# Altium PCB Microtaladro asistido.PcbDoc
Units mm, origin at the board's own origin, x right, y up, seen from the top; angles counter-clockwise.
Board outline 86.69 x 80.16 mm, 2 copper layers (Top Layer, Bottom Layer); 41 components, 54 nets, 188 pads, 36 vias.
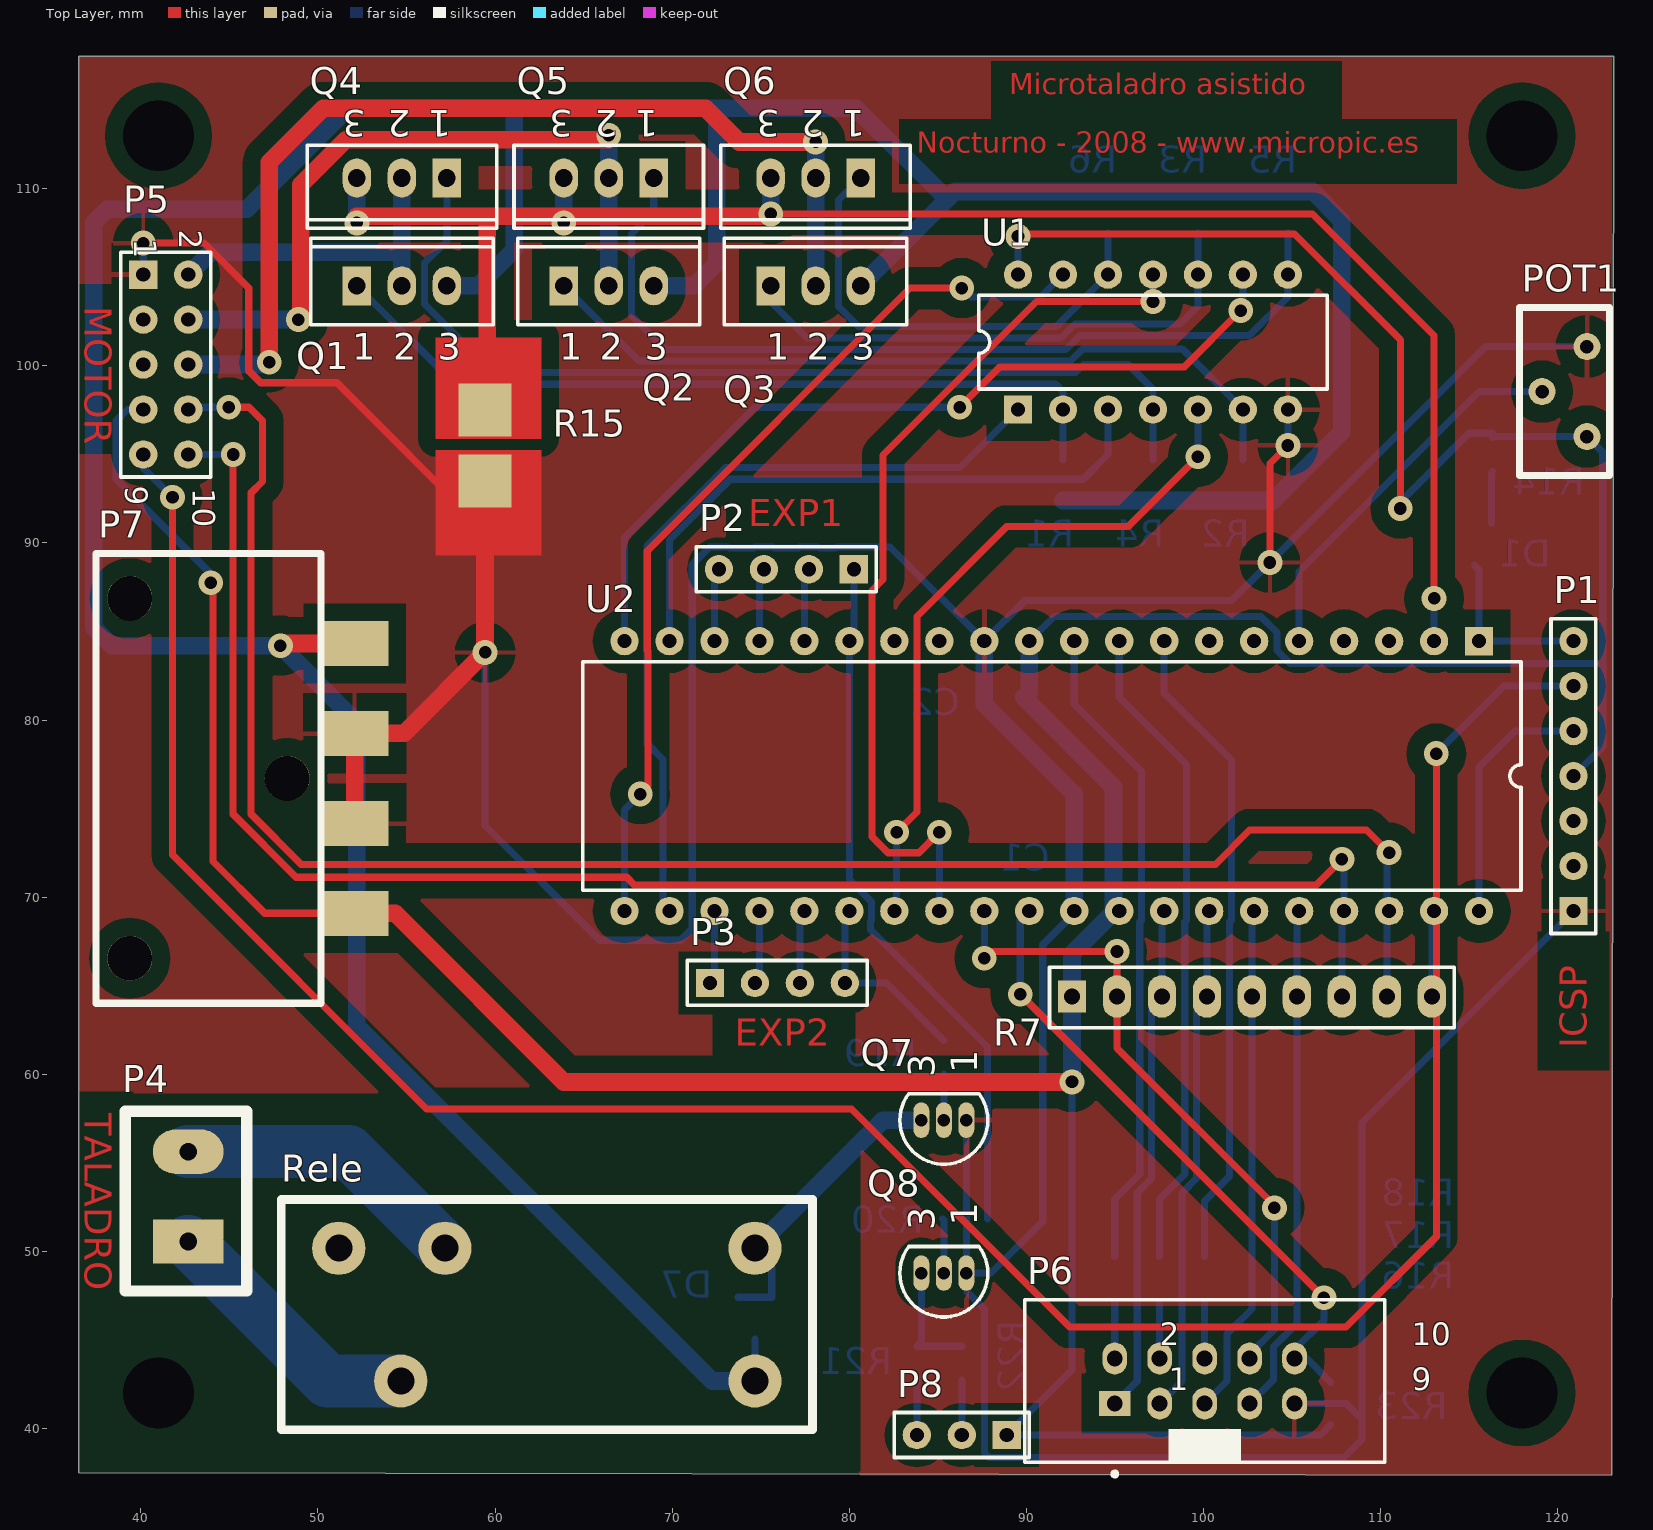
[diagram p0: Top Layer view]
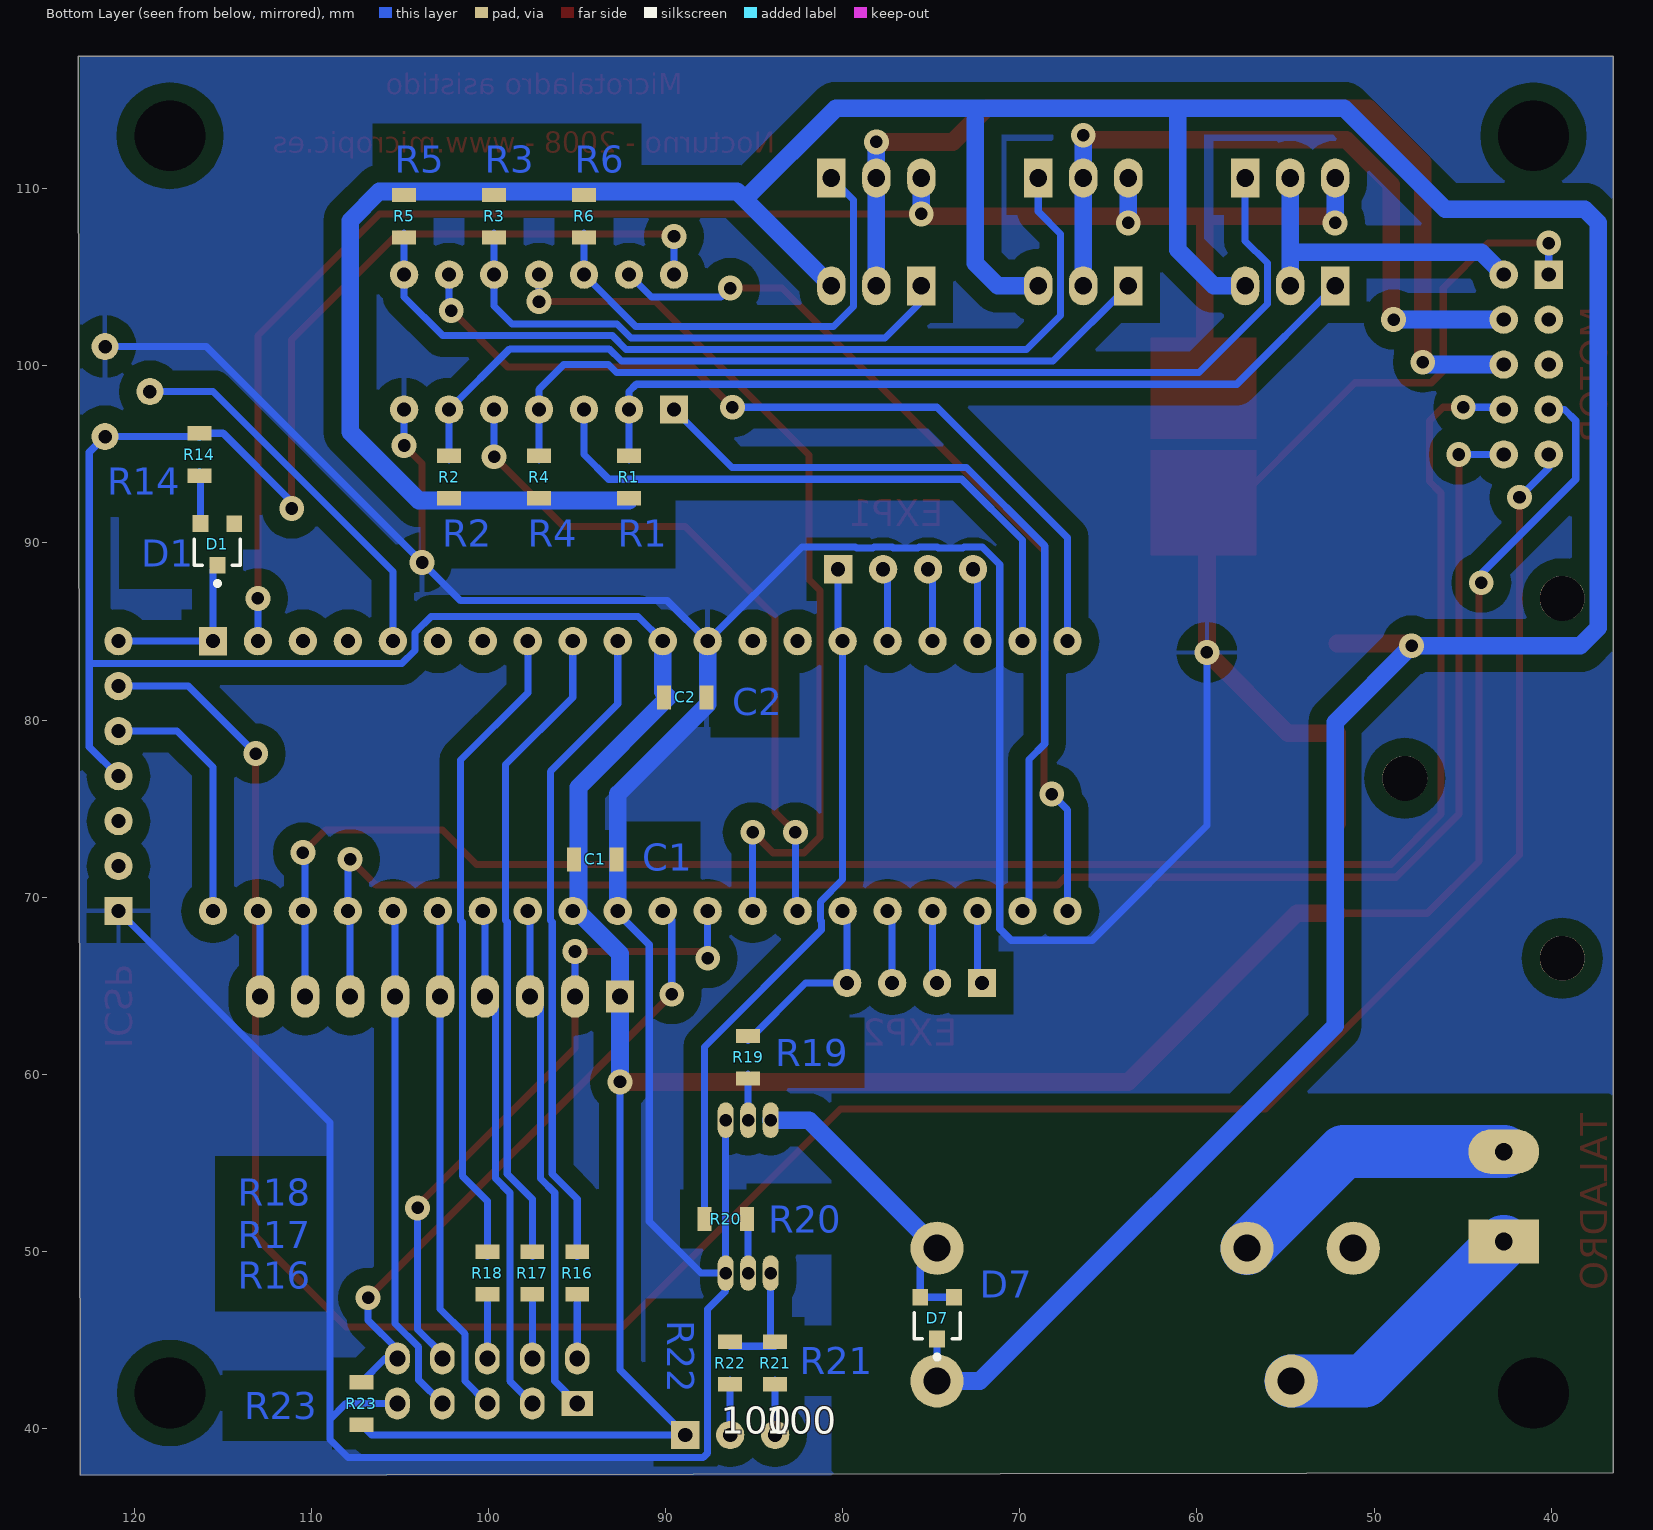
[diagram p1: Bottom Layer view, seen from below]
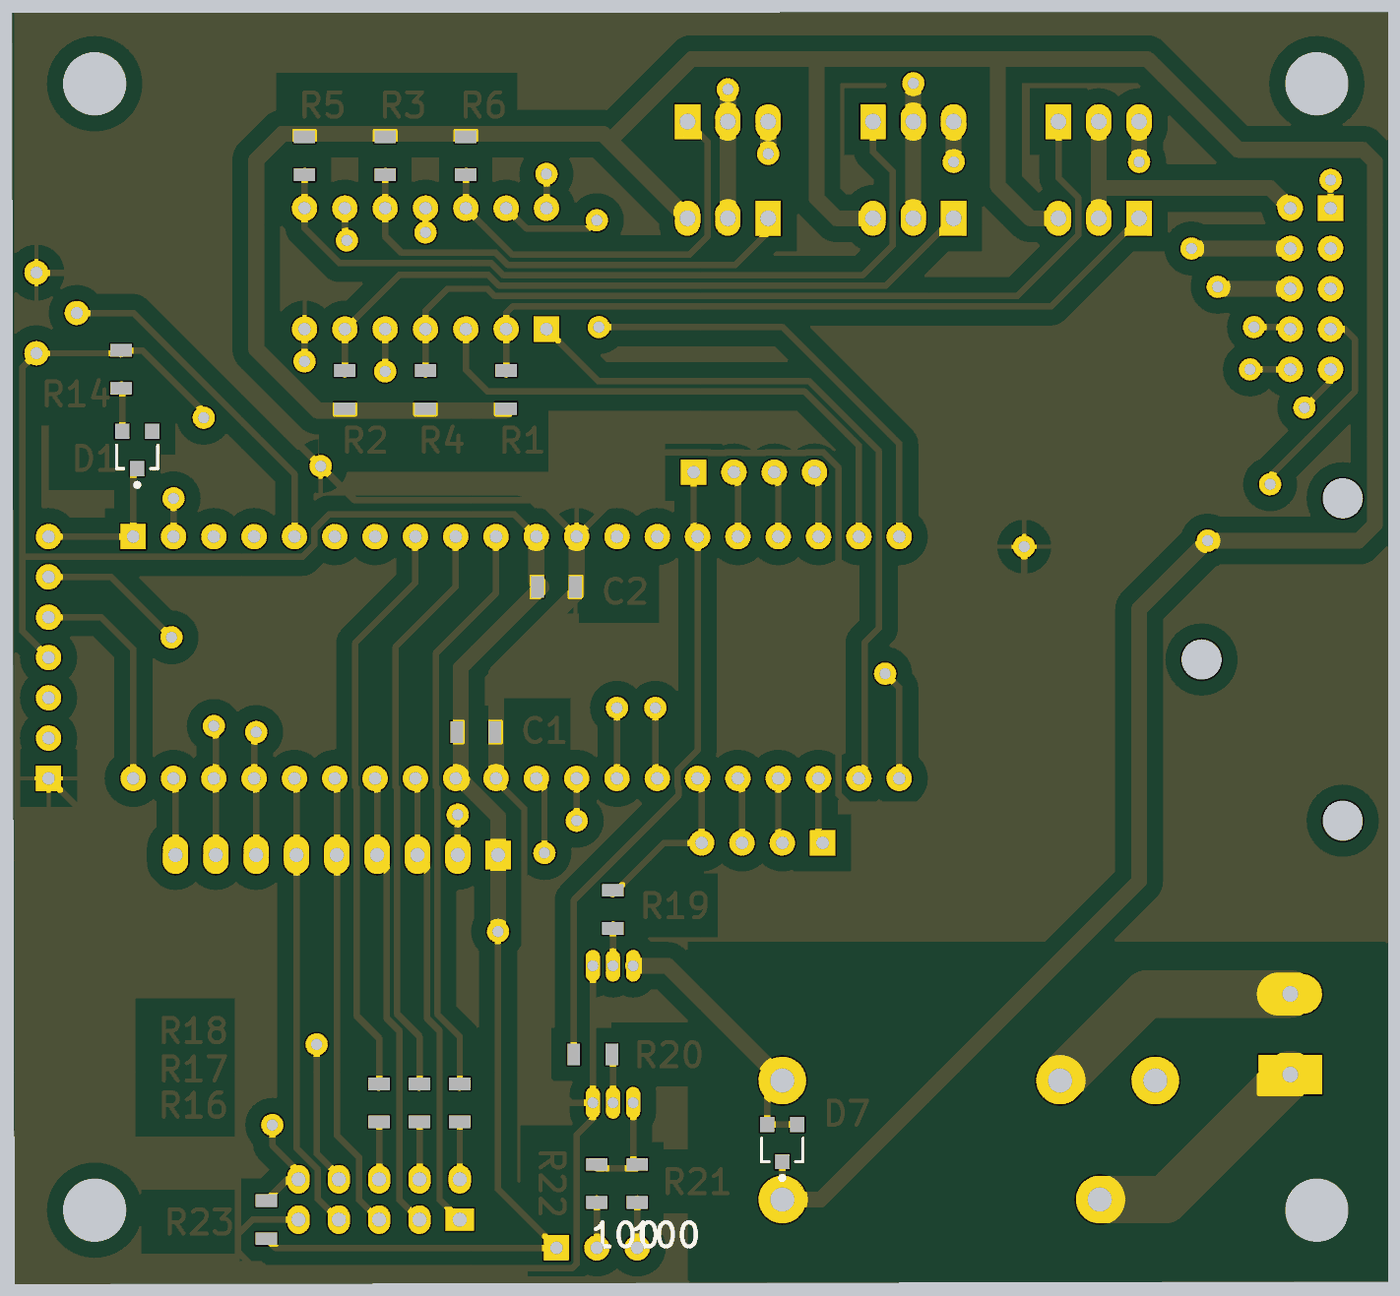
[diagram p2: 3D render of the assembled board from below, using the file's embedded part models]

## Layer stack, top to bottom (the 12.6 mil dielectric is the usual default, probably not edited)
Top Layer: signal copper 0.0356
Dielectric: dielectric 0.32, FR-4, Dk 4.8
Bottom Layer: signal copper 0.0356

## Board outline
36.5,37.5 123.063,37.338 123.19,117.475 36.5,117.5

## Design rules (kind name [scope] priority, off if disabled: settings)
Clearance [All] p1: gap=0.254
HoleSize [All] p1: absolutevalues=TRUE maxlimit=4 minlimit=0.025 maxpercent=80.000 minpercent=20.000
PolygonConnect [All] p1: connectstyle=Relief reliefconductorwidth=0.254 reliefentries=4 polygonreliefangle="90 Angle"
RoutingVias [All] p1: holewidth=0.6 width=1.4 viastyle="Through Hole" minholewidth=0.6 minwidth=1.4 maxholewidth=4 maxwidth=1.6
SilkscreenOverComponentPads [All] p1: minsilkscreentomaskgap=0.254
SolderMaskExpansion [All] p1: expansion=0.102
TestPointUsage [All] p1: valid=0 allowmultiple=FALSE
Testpoint [All] p1: side=15 testpointundercomponent=TRUE minsize=1.016 maxsize=2.54 preferedsize=1.524 minholesize=0 maxholesize=1.016 preferedholesize=0.813 testpointgrid=0.025 style=1023 order=0123456789
Width [All] p1: maxlimit=3 minlimit=0.254 preferedwidth=0.254 toplayer_prefwidth=0.4 bottomlayer_prefwidth=0.4 minimp=50.000000 maximp=50.000000 favimp=50.000000
22 further rules are at their usual default settings.

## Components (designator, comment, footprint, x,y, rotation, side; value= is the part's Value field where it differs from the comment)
C1 "100nF" 2012[0805] 93.98,72.136 r0 bottom
C2 "100nF" 2012[0805] 88.9,81.28 r0 bottom
D1 "BAV74" SOT23 115.316,89.916 r0 bottom
D7 "BAV74" SOT23 74.676,46.228 r0 bottom
P1 "ICSP" HDR1X7 120.904,69.215 r90 top
P2 "EXP1" HDR1X4 80.264,88.519 r180 top
P3 "EXP2" HDR1X4 72.136,65.151 r0 top
P4 "Taladro" Clema-2 42.672,46.736 r90 top
P5 "Motor" HDR2X5 40.132,105.156 r270 top
P6 "Pulsadores y leds" 918510X324 100.076,42.672 r0 top
P7 "Alimentación" "CONECTOR ALIMENTACIóN" 48.26,76.708 r90 top
P8 "Iluminación" HDR1X3 88.9,39.624 r180 top
POT1 "RPot SM" PCBComponent_1 120.396,98.552 r90 top
Q1 "TIP125" 221A-02 54.737,104.521 r0 top
Q2 "TIP125" 221A-02 66.421,104.521 r0 top
Q3 "TIP125" 221A-02 78.105,104.521 r0 top
Q4 "IRF531" TO-220AB 54.737,110.617 r180 top
Q5 "IRF531" TO-220AB 66.421,110.617 r180 top
Q6 "IRF531" TO-220AB 78.105,110.617 r180 top
Q7 "2N3904" TO-92A 85.344,57.404 r90 top
Q8 "2N3904" TO-92A 85.344,48.768 r90 top
R1 "4K7" 2012[0805] 92.075,93.726 r270 bottom
R2 "4K7" 2012[0805] 102.235,93.726 r270 bottom
R3 "4K7" 2012[0805] 99.695,108.458 r90 bottom
R4 "47K" 2012[0805] 97.155,93.726 r270 bottom
R5 "47K" 2012[0805] 104.775,108.458 r90 bottom
R6 "47K" 2012[0805] 94.615,108.458 r90 bottom
R7 "8 x 4K7" "ARRAY RESISTENCIAS SIP9" 103.124,64.516 r0 top
R14 "4K7" 2012[0805] 116.332,94.996 r90 bottom
R15 "0,1" "0603 Shunt" 59.436,95.504 r90 top
R16 "470" 2012[0805] 94.996,48.768 r90 bottom
R17 "470" 2012[0805] 97.536,48.768 r90 bottom
R18 "470" 2012[0805] 100.076,48.768 r90 bottom
R19 "10K" 2012[0805] 85.344,60.96 r90 bottom
R20 "10K" 2012[0805] 86.614,51.816 r0 bottom
R21 "100" 2012[0805] 83.82,43.688 r90 bottom
R22 "100" 2012[0805] 86.36,43.688 r90 bottom
R23 "4K7" 2012[0805] 107.188,41.402 r270 bottom
Rele "Zócalo Finder 95.13" "Zocalo rele" 74.676,42.672 r90 top
U1 "SN7404N" N014 97.155,101.346 r0 top
U2 "PIC18F4539-I/P" PDIP600-40 91.44,76.835 r180 top

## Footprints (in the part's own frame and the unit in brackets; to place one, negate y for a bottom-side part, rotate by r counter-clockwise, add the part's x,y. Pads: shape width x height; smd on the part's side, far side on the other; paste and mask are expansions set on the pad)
221A-02 [mm] "TO, Thru-Hole, Vertical, Heatsink Mounted; 3 In-Line Leads; Pitch 2.54 mm"
  rect 1.6x2.2 hole 1: 1(-2.54,0)
  oval 1.6x2.2 hole 1: 2(0,0) 3(2.54,0)
  silkscreen extent -5.15,-2.2 5.15,2.7
"0603 Shunt" [mm] "Resistencia Shunt 06 x 03 mm"
  rect 3x3 smd: 1(2,0) 2(-2,0)
2012[0805] [mm] "Chip Resistor; Body 2.0 x 1.3 mm (LxW typ)"
  rect 0.8x1.35 smd: 1(-1.2,0) 2(1.2,0)
  body extent -1,-0.62 1,0.64, height 0.43
918510X324 [mm] "Connector; IDC, Low Profile Male Header, Thru-Hole; 10 Position; Vertical; Pitch 2.54 mm; Body 20.32 x 9.2 x 9.45 mm (LxWxH)"
  rect 1.8x1.4 hole 0.9: 1(-5.08,-1.27)
  oval 1.4x1.8 hole 0.9: 2(-5.08,1.27) 3(-2.54,-1.27) 4(-2.54,1.27) 5(0,-1.27) 6(0,1.27) 7(2.54,-1.27) 8(2.54,1.27) 9(5.08,-1.27) 10(5.08,1.27)
  silkscreen extent -10.16,-5.37 10.16,4.6
"ARRAY RESISTENCIAS SIP9" [mm] "Array resistencias SIP9"
  rect 1.6x1.8 hole 0.9: 1(-10.541,-0.127)
  oval 1.6x2.4 hole 0.9: 2(-8.001,-0.127) 3(-5.461,-0.127) 4(-2.921,-0.127) 5(-0.381,-0.127) 6(2.159,-0.127) 7(4.699,-0.127) 8(7.239,-0.127) 9(9.779,-0.127)
  silkscreen extent -11.81,-1.91 11.05,1.52
Clema-2 [mm]
  rect 2.5x4 hole 1: 1(3.81,0)
  oval 2.5x4 hole 1: 2(8.89,0)
  silkscreen extent 1.02,-3.3 11.18,3.56, body extent 0.8,-3.72 11.3,3.98, height 10
"CONECTOR ALIMENTACIóN" [mm] "Conector alimentación"
  round 2.54 hole 2.54 unplated: 0(-10.16,8.89) 0(10.16,8.89)
  round 2.54 hole 2.54 unplated paste+0: 0(0,0)
  rect 2.54x3.81 smd: 1(7.62,-3.81) 2(2.54,-3.81) 3(-2.54,-3.81) 4(-7.62,-3.81)
  silkscreen extent -12.7,-1.91 12.7,10.8
HDR1X3 [mm] "Connector; Header; 3 Position"
  rect 1.6x1.6 hole 0.8: 1(0,0)
  round 1.6 hole 0.8: 2(2.54,0) 3(5.08,0)
  silkscreen extent -1.27,-1.27 6.35,1.27
HDR1X4 [mm] "Connector; Header; 4 Position"
  rect 1.6x1.6 hole 0.8: 1(0,0)
  round 1.6 hole 0.8: 2(2.54,0) 3(5.08,0) 4(7.62,0)
  silkscreen extent -1.27,-1.27 8.89,1.27
HDR1X7 [mm] "Connector; Header; 7 Position"
  rect 1.6x1.6 hole 0.8: 1(0,0)
  round 1.6 hole 0.8: 2(2.54,0) 3(5.08,0) 4(7.62,0) 5(10.16,0) 6(12.7,0) 7(15.24,0)
  silkscreen extent -1.27,-1.27 16.51,1.27
HDR2X5 [mm] "Connector; Header; 5x2 Position"
  rect 1.6x1.6 hole 0.8: 1(0,0)
  round 1.6 hole 0.8: 2(0,2.54) 3(2.54,0) 4(2.54,2.54) 5(5.08,0) 6(5.08,2.54) 7(7.62,0) 8(7.62,2.54) 9(10.16,0) 10(10.16,2.54)
  silkscreen extent -1.27,-1.27 11.43,3.81
N014 [mm] "DIP; 14 Leads; Row Spacing 7.62 mm; Pitch 2.54 mm"
  rect 1.6x1.6 hole 0.8: 1(-7.62,-3.81)
  round 1.6 hole 0.8: 2(-5.08,-3.81) 3(-2.54,-3.81) 4(0,-3.81) 5(2.54,-3.81) 6(5.08,-3.81) 7(7.62,-3.81) 8(7.62,3.81) 9(5.08,3.81) 10(2.54,3.81) 11(0,3.81) 12(-2.54,3.81) 13(-5.08,3.81) 14(-7.62,3.81)
  silkscreen extent -9.85,-2.65 9.85,2.65
PCBComponent_1 [mil]
  round 60 hole 30: CCW(100,-50) CW(-100,-50) W(0,50)
  silkscreen extent -187,-100 187,100
PDIP600-40 [mm] "DIP, Plastic; 40 Leads; Row Spacing 15.24 mm; Pitch 2.54 mm"
  rect 1.6x1.6 hole 0.8: 1(-24.13,-7.62)
  round 1.6 hole 0.8: 2(-21.59,-7.62) 3(-19.05,-7.62) 4(-16.51,-7.62) 5(-13.97,-7.62) 6(-11.43,-7.62) 7(-8.89,-7.62) 8(-6.35,-7.62) 9(-3.81,-7.62) 10(-1.27,-7.62) 11(1.27,-7.62) 12(3.81,-7.62) 13(6.35,-7.62) 14(8.89,-7.62) 15(11.43,-7.62) 16(13.97,-7.62) 17(16.51,-7.62) 18(19.05,-7.62) 19(21.59,-7.62) 20(24.13,-7.62) 21(24.13,7.62) 22(21.59,7.62) 23(19.05,7.62) 24(16.51,7.62) 25(13.97,7.62) 26(11.43,7.62) 27(8.89,7.62) 28(6.35,7.62) 29(3.81,7.62) 30(1.27,7.62) 31(-1.27,7.62) 32(-3.81,7.62) 33(-6.35,7.62) 34(-8.89,7.62) 35(-11.43,7.62) 36(-13.97,7.62) 37(-16.51,7.62) 38(-19.05,7.62) 39(-21.59,7.62) 40(-24.13,7.62)
  silkscreen extent -26.5,-6.45 26.5,6.45
SOT23 [mm] "SOT-23; 3 Leads; Body 3.1 x 2.5 mm, inc. leads (LxW max), Alternate Lead Configuration"
  rect 0.9x0.95 smd: 1(0,1.175) 2(0.95,-1.175) 3(-0.95,-1.175)
  silkscreen extent -1.3,-0.3 1.3,2.32, body extent -1.48,-1.25 1.52,1.25, height 1.08
TO-92A [mm] "TO, Flat Index; 3 In-Line, Axial Leads; Body Dia. 4.5mm; Leads 0.51 x 0.48 mm (max)"
  oval 2x0.9 hole 0.7: 1(0,-1.27) 2(0,0) 3(0,1.27)
  silkscreen extent -2.48,-2.48 1.5,2.48
TO-220AB [mm] "TO, Thru-Hole, Vertical, Heatsink Mounted; 3 In-Line Leads; Pitch 2.54 mm"
  rect 1.6x2.2 hole 1: 1(-2.54,0)
  oval 1.6x2.2 hole 1: 2(0,0) 3(2.54,0)
  silkscreen extent -5.35,-1.85 5.35,2.85
"Zocalo rele" [mm] "Zócalo relé"
  round 3 hole 1.524: 0(0,0) 1(7.5,0) 2(7.5,17.5) 3(0,20) 4(7.5,23.5)
  silkscreen extent -2.75,-3.25 10.25,26.75

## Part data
C1 C2: library part Cap, "Capacitor"
P1: library part "Header 7", "Header, 7-Pin"
P2 P3: library part MHDR1X4, "Header, 4-Pin"
P4: library part "Header 2", "Header, 2-Pin"
P5 P6: library part "Header 5X2", "Header, 5-Pin, Dual row"
P7: "Conector de alimentación compatible PC"
P8: library part "Header 3", "Header, 3-Pin"
POT1: "Square Trimming Potentiometer"
Q1 Q2 Q3: "Darlington Silicon Power PNP Transistor, 8 Amp, 60 Volts and 65 Watts"
Q4 Q5 Q6: library part IRF5210, "HEXFET Power MOSFET"
Q7 Q8: "NPN General Purpose Amplifier"
R1 R2 R3 R4 R5 R6 R14 R15 R16 R17 R18 R19 R20 R21 R22 R23: library part Res1, "Resistor"
R7: library part "Array Resistencias punto común SIP+8"
Rele: "Zócalo Finder 95.13 para Relé Finder 40.31"
U1: "Hex Inverter"
U2: "Enhanced FLASH Microcontroller with Single Phase Induction Motor Control Kernel, 24K FLASH, 40-Pin PDIP, Standard Volt Range, Industrial Temperature"

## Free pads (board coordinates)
  round 1.524 hole 4 unplated: 0(41,42) 0(41,113) 0(118,42) 0(118,113)

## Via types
v1: diameter 1.4, hole 0.711, Top Layer to Bottom Layer, 36 vias

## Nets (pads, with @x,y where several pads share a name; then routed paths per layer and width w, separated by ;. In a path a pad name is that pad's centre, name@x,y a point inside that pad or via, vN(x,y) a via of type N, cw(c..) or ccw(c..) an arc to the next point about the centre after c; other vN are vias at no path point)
+12: D7.1 P7.1 Q1.3 Q2.3 Q3.3 R1.2 R2.2 R3.2 R4.2 R5.2 R6.2 Rele.0 | length 232
  Top Layer w1: v1(47.879,84.201) 48.006,84.328 P7.1
  Bottom Layer w0.4: Rele.0 D7.1
  Bottom Layer w1: Q1.3 59.055,104.521 61.087,106.553 61.087,114.554 ; Q2.3 71.247,104.521 72.517,105.791 72.517,113.919 ; Rele.0 72.263,42.672 52.197,62.738 52.197,79.883 v1(47.879,84.201) 38.354,84.201 37.338,85.217 37.338,108.077 38.1,108.839 45.974,108.839 51.689,114.554 61.087,114.554 ; Q3.3 85.532,109.408 ; R1.2@92.075,92.395 103.952,92.395 107.823,96.266 107.823,108.204 106.172,109.855 93.853,109.855 ; R6.2@94.168,109.855 85.979,109.855 85.532,109.408 ; 61.087,114.554 80.386,114.554 85.532,109.408
GND: C1.1 C2.1 P1.1 P5.1 P6.9 P7.2 P7.3 POT1.CCW Q7.1 Q8.1 R15.2 U1.7 U2.12 U2.31 | length 287.8
  Top Layer w0.4: v1(40.132,106.934) 43.561,106.934 46.09,104.405 46.09,99.725 46.766,99.049 51.065,99.049 59.436,90.678 ; v1(103.759,88.9) 103.759,94.488 v1(104.775,95.504)
  Top Layer w1: P7.3 P7.2 54.864,79.248 v1(59.436,83.82) 59.436,90.678
  Bottom Layer w0.4: P5.1 v1(40.132,106.934) ; v1(59.436,83.82) 59.436,74.041 65.913,67.564 70.485,67.564 71.136,68.215 71.136,88.784 72.125,89.773 73.163,89.773 73.213,89.723 74.615,89.723 74.665,89.773 75.703,89.773 75.753,89.723 77.155,89.723 77.205,89.773 78.243,89.773 78.293,89.723 79.226,89.723 79.276,89.773 82.312,89.773 U2.12 89.916,86.741 101.6,86.741 115.951,101.092 POT1.CCW ; Q7.1 Q8.1 ; U2.31@92.71,69.088 90.932,67.31 90.932,51.689 88.011,48.768 Q8.1 ; v1(104.775,95.504) U1.7 ; P6.9 108.067,41.402 108.966,40.503 ; 108.966,39.878 108.966,40.503 ; P1.1 108.966,57.277 108.966,40.503 ; Q8.1 86.614,47.752 87.63,46.736 87.63,38.608 87.884,38.354 107.95,38.354 108.966,39.37 108.966,40.503
  Bottom Layer w1: U2.12 87.63,80.899 92.71,75.819 U2.31@92.71,69.088
GND_VIRTUAL: Q4.3 Q5.3 Q6.3 R15.1 U2.2 | length 98.4
  Top Layer w0.4: v1(75.565,108.585) 106.172,108.585 113.03,101.727 v1(113.03,86.868)
  Top Layer w1: v1@52.197,108.458 59.563,108.458 ; R15.1@59.563,97.79 59.563,108.458 ; v1(75.565,108.585) 75.438,108.458 63.881,108.458 59.563,108.458
  Bottom Layer w0.4: U2.2 v1(113.03,86.868)
  Bottom Layer w1: v1@52.197,108.458 Q4.3 ; v1(63.881,108.077) Q5.3 ; v1(75.565,108.585) Q6.3
  other v1: 52.197,108.077
NetD1_1: D1.1 P1.7 U2.1 | length 9.7
  Bottom Layer w0.4: D1.1 115.57,88.487 U2.1 P1.7
NetD1_2: D1.2 R14.1 | length 3
  Bottom Layer w0.4: D1.2 116.266,93.98 R14.1@116.332,94.046
NetD2_1: P6.2 R16.1 | length 3.2
  Bottom Layer w0.4: P6.2 94.996,47.117
NetD3_1: P6.4 R17.1 | length 3.2
  Bottom Layer w0.4: P6.4 97.536,47.117
NetD4_1: P6.6 R18.1 | length 3.2
  Bottom Layer w0.4: P6.6 100.076,47.117
NetD5_2: P8.3 R21.1 | length 3.1
  Bottom Layer w0.4: P8.3 R21.1@83.82,42.738
NetD6_2: P8.2 R22.1 | length 3.1
  Bottom Layer w0.4: P8.2 R22.1@86.36,42.738
NetD7_2: D7.2 D7.3 Q7.3 Rele.1 | length 17.5
  Bottom Layer w0.4: D7.3 D7.2 75.626,49.088 74.676,50.038 Rele.1
  Bottom Layer w1: Rele.1 81.908,57.404 Q7.3
NetP1_5: P1.5 U2.40 | length 14.3
  Bottom Layer w0.4: U2.40 115.57,77.343 117.602,79.375 P1.5
NetP1_6: P1.6 P5.9 R7.9 U2.39 | length 149.1
  Top Layer w0.4: v1(41.783,92.583) 41.783,72.39 56.134,58.039 80.137,58.039 92.456,45.72 108.058,45.72 113.157,50.819 v1(113.157,78.105)
  Bottom Layer w0.4: P5.9 40.132,94.234 v1(41.783,92.583) ; R7.9 U2.39@112.903,68.834 ; v1@113.03,77.978 v1(113.157,78.105) 116.967,81.915 P1.6
NetP2_1: P2.1 R20.2 U2.15 | length 40.1
  Bottom Layer w0.4: P2.1 80.264,84.709 U2.15 80.01,70.988 81.264,69.734 81.264,68.696 81.214,68.646 81.214,68.138 87.814,61.538 R20.2
NetP2_2: P2.2 U2.16 | length 4.2
  Bottom Layer w0.4: U2.16 77.47,88.265 P2.2
NetP2_3: P2.3 U2.17 | length 4.2
  Bottom Layer w0.4: U2.17 74.93,88.265 P2.3
NetP2_4: P2.4 U2.18 | length 4.2
  Bottom Layer w0.4: U2.18 72.39,88.265 P2.4
NetP3_1: P3.1 U2.23 | length 4.2
  Bottom Layer w0.4: P3.1 72.39,65.405 U2.23
NetP3_2: P3.2 U2.24 | length 4.2
  Bottom Layer w0.4: P3.2 74.93,65.405 U2.24
NetP3_3: P3.3 U2.25 | length 4.2
  Bottom Layer w0.4: P3.3 77.216,68.961 U2.25
NetP3_4: P3.4 R19.2 U2.26 | length 11.1
  Bottom Layer w0.4: U2.26 79.756,68.961 P3.4 82.103,65.151 R19.2@85.344,61.91
NetP4_1: P4.1 Rele.3 | length 15.3
  Bottom Layer w3: P4.1 50.546,42.672 Rele.3
NetP4_2: P4.2 Rele.2 | length 16.8
  Bottom Layer w3: P4.2 51.722,55.626 Rele.2
NetP5_2: P5.2 Q1.2 Q4.2 | length 18.7
  Bottom Layer w1: P5.2 43.942,106.426 54.737,106.426 ; Q1.2 54.737,106.426 ; Q4.2 54.737,106.426
NetP5_4: P5.4 Q2.2 Q5.2 | length 40.6
  Top Layer w1: v1(48.895,102.616) 49.022,102.743 49.022,110.236 51.562,112.776 v1@66.421,112.776
  Bottom Layer w1: P5.4 v1(48.895,102.616) ; Q2.2 Q5.2 v1@66.421,112.776
  other v1: 66.421,113.03
NetP5_6: P5.6 Q3.2 Q6.2 | length 57
  Top Layer w1: v1(47.244,100.203) 47.244,111.506 50.292,114.554 71.882,114.554 73.787,112.649 v1(78.105,112.649)
  Bottom Layer w1: P5.6 47.117,100.076 v1(47.244,100.203) ; Q3.2 Q6.2 v1(78.105,112.649)
NetP5_8: P5.8 R7.8 U2.38 | length 102
  Top Layer w0.4: v1(44.958,97.663) 46.101,97.663 46.863,96.901 46.863,93.472 46.228,92.837 46.228,74.676 49.052,71.852 100.681,71.852 102.616,73.787 109.22,73.787 v1(110.49,72.517)
  Bottom Layer w0.4: P5.8 42.799,97.663 v1(44.958,97.663) ; R7.8 110.363,72.39 v1(110.49,72.517)
NetP5_10: P5.10 R7.7 U2.37 | length 95.2
  Top Layer w0.4: v1(45.212,94.996) 45.212,74.676 48.768,71.12 67.437,71.12 67.883,70.674 106.361,70.674 v1(107.823,72.136)
  Bottom Layer w0.4: P5.10 v1(45.212,94.996) ; R7.7 U2.37@107.823,68.834 ; v1(107.823,72.136) 107.95,72.009 U2.37
NetP6_1: P6.1 R7.3 U2.33 | length 28.5
  Bottom Layer w0.4: P6.1 96.266,42.672 96.266,53.304 97.063,54.101 97.063,63.789 R7.3 U2.33@97.663,68.834
NetP6_3: P6.3 R7.4 U2.34 | length 28.5
  Bottom Layer w0.4: P6.3 98.806,42.672 98.806,53.304 99.603,54.101 99.603,63.789 R7.4 U2.34@100.203,68.834
NetP6_5: P6.5 R7.5 U2.35 | length 28.5
  Bottom Layer w0.4: P6.5 101.346,42.672 101.346,45.339 102.743,46.736 R7.5 U2.35@102.743,68.834
NetP6_7: P6.7 R7.6 U2.36 | length 28.5
  Bottom Layer w0.4: P6.7 103.952,42.738 103.952,44.591 105.283,45.922 R7.6 U2.36@105.283,68.834
NetP6_8: P6.8 R7.2 U2.29 | length 40.1
  Top Layer w0.4: v1(87.63,66.548) 88.011,66.929 v1(95.123,66.929) R7.2 95.123,61.468 104.013,52.578 v1(104.013,52.451)
  Bottom Layer w0.4: v1(87.63,66.548) 87.63,67.215 87.63,68.548 U2.29 ; R7.2 v1(95.123,66.929) ; P6.8 102.616,44.18 104.013,45.577 v1(104.013,52.451)
NetP6_10: P6.10 R23.1 U2.30 | length 35.9
  Top Layer w0.4: v1(89.662,64.516) v1(106.807,47.371)
  Bottom Layer w0.4: v1(89.662,64.516) 89.662,68.707 U2.30 ; v1(106.807,47.371) 106.807,46.101 105.156,44.45 P6.10 105.848,43.942 R23.1
NetPOT1_W: POT1.W U2.5 | length 21.9
  Bottom Layer w0.4: U2.5 105.41,88.392 115.57,98.552 POT1.W
NetQ1_1: Q1.1 R1.1 U1.2 | length 46.2
  Bottom Layer w0.4: Q1.1 57.753,98.965 91.662,98.965 92.075,98.552 U1.2 R1.1@92.075,94.676
NetQ2_1: Q2.1 R2.1 U1.6 | length 44.7
  Bottom Layer w0.4: Q2.1 68.129,100.273 92.507,100.273 93.199,100.965 98.806,100.965 U1.6 R2.1@102.235,94.676
NetQ3_1: Q3.1 R3.1 U1.10 | length 30.7
  Bottom Layer w0.4: Q3.1 75.565,103.632 77.616,101.581 91.965,101.581 92.746,102.362 98.679,102.362 99.695,103.378 U1.10 R3.1@99.695,107.508
NetQ4_1: Q4.1 R4.1 U1.4 | length 55.2
  Bottom Layer w0.4: Q4.1 57.277,107.061 56.023,105.807 56.023,103.489 59.893,99.619 92.778,99.619 93.235,100.076 95.758,100.076 97.155,98.679 U1.4 R4.1@97.155,94.676
NetQ5_1: Q5.1 R5.1 U1.8 | length 51
  Bottom Layer w0.4: Q5.1 68.961,108.712 67.707,107.458 67.707,102.854 69.634,100.927 92.236,100.927 93.017,101.708 102.597,101.708 104.775,103.886 R5.1@104.775,107.508
NetQ6_1: Q6.1 R6.1 U1.12 | length 27
  Bottom Layer w0.4: Q6.1 79.391,109.363 79.391,103.362 80.518,102.235 91.694,102.235 U1.12 R6.1@94.615,107.508
NetQ7_2: Q7.2 R19.1 | length 2.6
  Bottom Layer w0.4: Q7.2 R19.1@85.344,60.01
NetQ8_2: Q8.2 R20.1 | length 3.1
  Bottom Layer w0.4: R20.1@85.278,51.816 85.344,51.75 Q8.2
NetQ8_3: Q8.3 R21.2 R22.2 | length 6.8
  Bottom Layer w0.4: Q8.3 84.074,44.892 83.82,44.638 R22.2@86.36,44.638
NetR16_2: R16.2 U2.10 | length 36.9
  Bottom Layer w0.4: U2.10 92.71,80.899 96.504,77.105 96.504,68.696 96.409,68.601 96.409,54.372 94.996,52.959 R16.2@94.996,49.718
NetR17_2: R17.2 U2.9 | length 36.9
  Bottom Layer w0.4: U2.9 95.25,81.28 99.044,77.486 99.044,68.696 98.949,68.601 98.949,54.372 97.536,52.959 R17.2@97.536,49.718
NetR18_2: R18.2 U2.8 | length 36.9
  Bottom Layer w0.4: U2.8 97.79,81.534 101.584,77.74 101.584,68.696 101.489,68.601 101.489,54.245 100.076,52.832 R18.2@100.076,49.718
NetU1_1: U1.1 U2.22 | length 45.3
  Bottom Layer w0.4: U2.22 69.485,69.58 69.485,77.774 68.596,78.663 68.596,89.841 73.008,94.253 86.252,94.253 U1.1
NetU1_3: U1.3 U2.19 | length 35
  Bottom Layer w0.4: U2.19 69.85,90.17 73.279,93.599 93.218,93.599 94.615,94.996 U1.3
NetU1_5: U1.5 U2.27 | length 39.4
  Top Layer w0.4: v1(82.677,73.66) 83.82,74.803 83.82,85.852 88.9,90.932 95.758,90.932 v1(99.695,94.869)
  Bottom Layer w0.4: U2.27 82.677,69.342 v1(82.677,73.66) ; v1(99.695,94.869) U1.5
NetU1_9: U1.9 U2.20 | length 48
  Top Layer w0.4: v1(86.233,97.663) 88.519,99.949 98.933,99.949 v1(102.108,103.124)
  Bottom Layer w0.4: U2.20 67.31,90.297 74.676,97.663 v1(86.233,97.663) ; v1(102.108,103.124) 102.235,103.251 U1.9
NetU1_11: U1.11 U2.28 | length 51.3
  Top Layer w0.4: v1(85.09,73.66) 83.936,72.506 82.199,72.506 81.296,73.409 81.296,87.309 81.915,87.928 81.915,94.977 90.57,103.632 v1(97.155,103.632)
  Bottom Layer w0.4: U2.28 v1(85.09,73.66) ; v1(97.155,103.632) U1.11
NetU1_13: U1.13 U2.21 | length 51.3
  Top Layer w0.4: v1(68.199,75.819) 68.646,76.266 68.646,83.886 68.596,83.936 68.596,89.551 83.439,104.394 v1(86.36,104.394)
  Bottom Layer w0.4: U2.21 67.31,74.93 v1(68.199,75.819) ; v1(86.36,104.394) 86.868,103.886 90.805,103.886 U1.13
VCC: C1.2 C2.2 P1.4 P5.7 P7.4 P8.1 POT1.CW R7.1 R14.2 R23.2 U1.14 U2.11 U2.32 | length 253.5
  Top Layer w0.4: v1@44.069,87.503 44.069,72.009 46.99,69.088 P7.4 ; v1(89.535,107.315) 89.662,107.442 105.156,107.442 111.125,101.473 v1(111.125,91.948)
  Top Layer w1: P7.4 54.356,69.088 63.881,59.563 v1(92.583,59.563)
  Bottom Layer w0.4: P5.7 39.243,97.536 38.608,96.901 38.608,93.599 v1@44.196,88.011 ; U1.14 v1(89.535,107.315) ; U2.11 91.567,85.852 103.246,85.852 104.156,84.942 104.156,83.936 104.907,83.185 122.555,83.185 ; v1(92.583,59.563) 92.583,43.307 P8.1 106.61,39.624 R23.2 ; v1(111.125,91.948) 111.125,92.329 114.992,96.196 R14.2 ; R14.2@116.332,95.946 116.398,96.012 POT1.CW 122.555,95.123 122.555,83.185 ; P1.4 122.555,78.486 122.555,83.185
  Bottom Layer w1: U2.11 90.17,81.6 89.85,81.28 94.93,76.2 94.93,72.136 94.93,69.535 94.93,69.149 92.583,66.802 R7.1 v1(92.583,59.563)
  other v1: 43.942,87.757
pads on no net: D1.3 P1.2 P1.3 P5.3 P5.5 P7.0 Rele.4 U2.3 U2.4 U2.6 U2.7 U2.13 U2.14

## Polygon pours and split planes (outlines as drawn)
GND on Top Layer "Bottom Layer-No Net" (solid): 80.518,37.465 80.645,37.592 80.645,58.928 36.703,58.928 36.576,58.801 36.449,58.928 36.449,117.475 123.063,117.475 123.063,37.338 80.645,37.338 80.518,37.465
GND on Bottom Layer "Bottom Layer-No Net" (solid): 80.518,37.465 80.645,37.592 80.645,58.928 36.703,58.928 36.576,58.801 36.449,58.928 36.449,117.475 123.063,117.475 123.063,37.338 80.645,37.338 80.518,37.465

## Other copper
Top Layer:
  rectangle net GND: 56.642,89.281 62.611,95.25
  rectangle net GND_VIRTUAL: 56.642,95.885 62.611,101.6
  text "Microtaladro asistido" at 89.027,114.935 h2
  text "Nocturno - 2008 - www.micropic.es" at 83.82,111.633 h2
  text "MOTOR" at 36.83,103.378 h1.52 r270
  text "EXP1" at 74.295,90.932 h1.52
  text "EXP2" at 73.533,61.595 h1.52
  text "ICSP" at 121.666,61.468 h1.52 r90
  text "TALADRO" at 36.83,57.785 h1.52 r270

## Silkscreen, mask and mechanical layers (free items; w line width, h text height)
Mechanical 1:
  lines w0.4: 35.687,37.719 35.687,118.237 123.317,118.237 123.825,117.729 123.825,36.703 36.703,36.703 35.687,37.719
